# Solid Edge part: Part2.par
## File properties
Author: Deepak Maini
Template: Normal.par
Last saved by: CADCIM
Revision: 5
Application: Solid Edge
Accuracy: 0.99
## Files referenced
..\Asm2.asm
7C:\solid-edge-14\c09-sldedg-14-042104\parallel\Asm2.asm
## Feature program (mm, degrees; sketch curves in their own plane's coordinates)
sketch for "unnamed Protrusion 1" plane through (0, 0, 0) normal (0, 0, 1) x-axis (1, 0, 0)
  circle centre (0, 0) radius 7
extrude "unnamed Protrusion 1" add finite 13 along +normal
sketch for "ExtrudedProtrusion_2" plane through (0, 0, 13) normal (0, 0, 1) x-axis (0, 1, 0)
  circle centre (0, 0) radius 8.8981
extrude "ExtrudedProtrusion_2" add finite 60.325 along +normal
sketch for "ExtrudedProtrusion_3" plane through (0, 0, 73.325) normal (0, 0, 1) x-axis (0, 1, 0)
  circle centre (0, 0) radius 7
extrude "ExtrudedProtrusion_3" add finite 13 along +normal
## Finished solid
Body 1: solid body, 7 faces, 6 edges, 0 vertices.
  Faces by surface: plane 4, cylinder 3
  Edges by curve: circle 6
Bounding box of the edges (mm): 17.796 x 17.796 x 86.325, from (-8.8981, -8.8981, 0) to (8.8981, 8.8981, 86.325).
Cylindrical faces by radius (mm): R7 x2, R8.8981 x1
Planar faces by outward normal: +z 2, -z 2
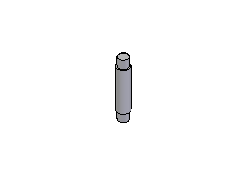
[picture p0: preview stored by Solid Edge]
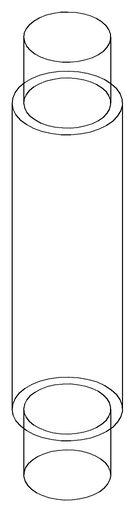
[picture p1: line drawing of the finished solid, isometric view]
